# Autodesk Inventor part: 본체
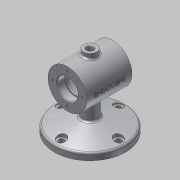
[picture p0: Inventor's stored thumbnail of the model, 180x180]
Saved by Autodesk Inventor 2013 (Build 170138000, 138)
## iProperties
Created: 2018-12
Part Number: 본체
Material: 알루미늄 6061
Document SubType Name: Modeling
Designer: Administrator
Density: 2.71 g/cm^3
Mass: 671.663 g
Surface Area: 552.366 cm^2
Volume: 247.846 cm^3
Author: Administrator
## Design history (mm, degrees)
sketch "스케치2"
  geometry: L1 (-35, 0)-(35, 0); L2 (0, 0)-(0, 30); L3 (-35, 16)-(-23, 16); L4 (-23, 14)-(-20, 14); L5 (-20, 14)-(-20, 25); L6 (-20, 25)-(0, 25); L7 (-35, 16)-(-35, 30); L8 (-35, 30)-(0, 30); L9 (-23, 16)-(-23, 14); L10 (35, 16)-(23, 16); L11 (23, 14)-(20, 14); L12 (20, 14)-(20, 25); L13 (20, 25)-(0, 25); L14 (35, 16)-(35, 30); L15 (35, 30)-(0, 30); L16 (23, 16)-(23, 14); 1 further point
  constraints: 32 end point, 6 symmetric about line, 4 perpendicular, 2 coincident, 2 parallel, 1 horizontal, 1 midpoint, 1 point on line, 1 vertical alignment
  dimensions: "d0" = 70 distance of L1.start L1.end; "d3" = 32 diameter of L3 L1; "d4" = 28 diameter of L4 L1; "d5" = 12 distance of L3.start L3.end; "d6" = 3 distance of L4.start L4.end; "d7" = 50 diameter of L6 L1; "d8" = 20 distance of L5.end L6.end; "d9" = 60 diameter of L8 L1
revolve "회전1" sketch "스케치2" stored, may be unused: angle "d10" = 90 deg
node "작업 평면1"
sketch "스케치4"
  geometry: C1 r 55 at (0, 0); 1 further point
  constraints: 1 centre point, 1 coincident
  dimensions: "d12" = 110 diameter of C1
extrude "돌출1" join sketch "스케치4" distance "d14" = 11; taper "d15" = 0 deg
sketch "스케치6"
  geometry: C1 r 55 at (0, 0) reference; C2 r 12 at (0, 0)
  constraints: 1 centre point, 1 coincident
  dimensions: "d16" = 24 diameter of C2
extrude "돌출2" join sketch "스케치6" stored distance "d18" = 10; taper "d19" = 0 deg
node "작업 평면2"
sketch "스케치7"
  geometry: C1 r 10 at (0, 0); 1 further point
  constraints: 1 centre point, 1 coincident
  dimensions: "d21" = 20 diameter of C1
extrude "돌출3" join sketch "스케치7" stored distance "d23" = 10; taper "d24" = 0 deg
sketch "스케치8"
  geometry: C1 r 10 at (0, 0) reference; C2 r 5 at (0, 0)
  constraints: 1 centre point, 1 coincident
  dimensions: "d25" = 10 diameter of C2
extrude "돌출4" cut sketch "스케치8" stored distance "d27" = 10; taper "d28" = 0 deg
node "작업 평면3"
sketch "스케치10"
  geometry: 2 further points
  constraints: 1 coincident, 1 other
feature "엠보싱1" sketch "스케치10" dims "d0" = 70, "d3" = 32, "d4" = 28, "d5" = 12, "d6" = 3, "d7" = 50, "d8" = 20, "d9" = 60, "d29" = 0.5, "d30" = 0
chamfer "모따기1" distance "d31" = 1; stored, may be unused: second distance "d32" = 2, angle "d33" = 45 deg
sketch "스케치11"
  geometry: C1 r 30 at (0, 0) reference; 1 further point
  constraints: 1 vertical alignment
  dimensions: "d34" = 23 distance of C1.centre point (0, 23)
hole "구멍1" sketch "스케치11" at (0, 23) diameter "d35" = 3.242; stored, may be unused: countersink angle "d39" = 90 deg, drill point angle "d41" = 118 deg; dims "d36" = 8, "d37" = 4, "d38" = 2, "d40" = 10
fillet "모깎기1" dims "d45" = 3
sketch "스케치12"
  geometry: L1 (-64, -12)-(-27.495, -12) reference; L2 (-64, 52)-(-64, -52) reference; L3 (-75, -55)-(-67, -55) reference; L4 (-75, 55)-(-75, -55) reference; L5 (-53.176, -12)-(-64.102, -52.776); L6 (0, 0)-(-76.327, 0); A1 r 3 centre (-67, -52) between (-67, -55) and (-64, -52) reference
  constraints: 4 end point, 1 perpendicular, 1 point on circle, 1 point on line, 1 tangent
  dimensions: "d52" = 75 deg angle of L3 L5
revolve "회전2" sketch "스케치12" stored, may be unused: angle "d53" = 90 deg
fillet "모깎기2" dims "d54" = 3
sketch "스케치13"
  geometry: C1 r 55 at (0, 0) reference; C2 r 4.5 at (44, 0)
  constraints: 1 centre point, 1 horizontal alignment
  dimensions: "d55" = 9 diameter of C2; "d57" = 44 distance of C1.centre C2.centre
extrude "돌출5" cut sketch "스케치13" distance "d58" = 10; taper "d59" = 0 deg
sketch "스케치14"
  geometry: C1 r 4.5 at (0, 0) reference; C2 r 7 at (0, 0); 1 further point
  constraints: 1 centre point, 1 coincident
  dimensions: "d60" = 14 diameter of C2
extrude "돌출6" cut sketch "스케치14" stored distance "d62" = 10; taper "d63" = 0 deg
sketch "스케치15"
  geometry: C1 r 4.5 at (0, 0) reference; 4 further points
  constraints: 3 other
extrude "돌출7" cut sketch "스케치15" stored distance "d67" = 10; taper "d68" = 0 deg
chamfer "모따기2" distance "d69" = 1; stored, may be unused: second distance "d70" = 2, angle "d71" = 45 deg
fillet "모깎기3" dims "d72" = 3
fillet "모깎기4" dims "d73" = 0.3
node "솔리드1"
pattern_circular "원형 패턴1" dims angle "d43" = 360 deg
mirror "대칭1"
pattern_circular "원형 패턴2" dims angle "d65" = 360 deg
node "투영된 루프1"
other parameters: "d11" = -75, "d20" = -112
